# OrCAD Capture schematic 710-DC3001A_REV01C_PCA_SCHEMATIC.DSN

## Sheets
1 PAGE2: size A; company: ANALOG DEVICES; note: DEMO BOARD BILL OF MATERIALS; note: LOW QUIESCENT CURRENT IDEAL DIODE WITH SHUTDOWN MODE
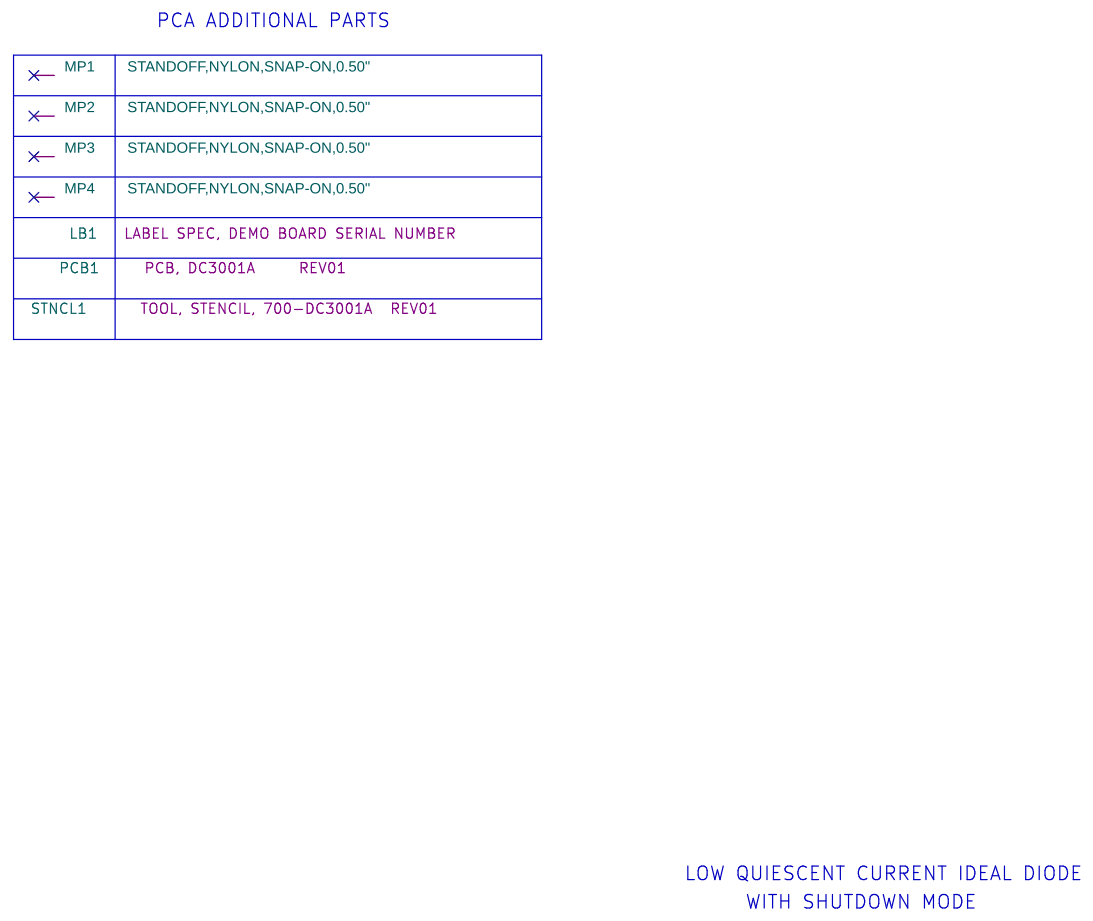
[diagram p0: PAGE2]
2 PAGE1: size Custom
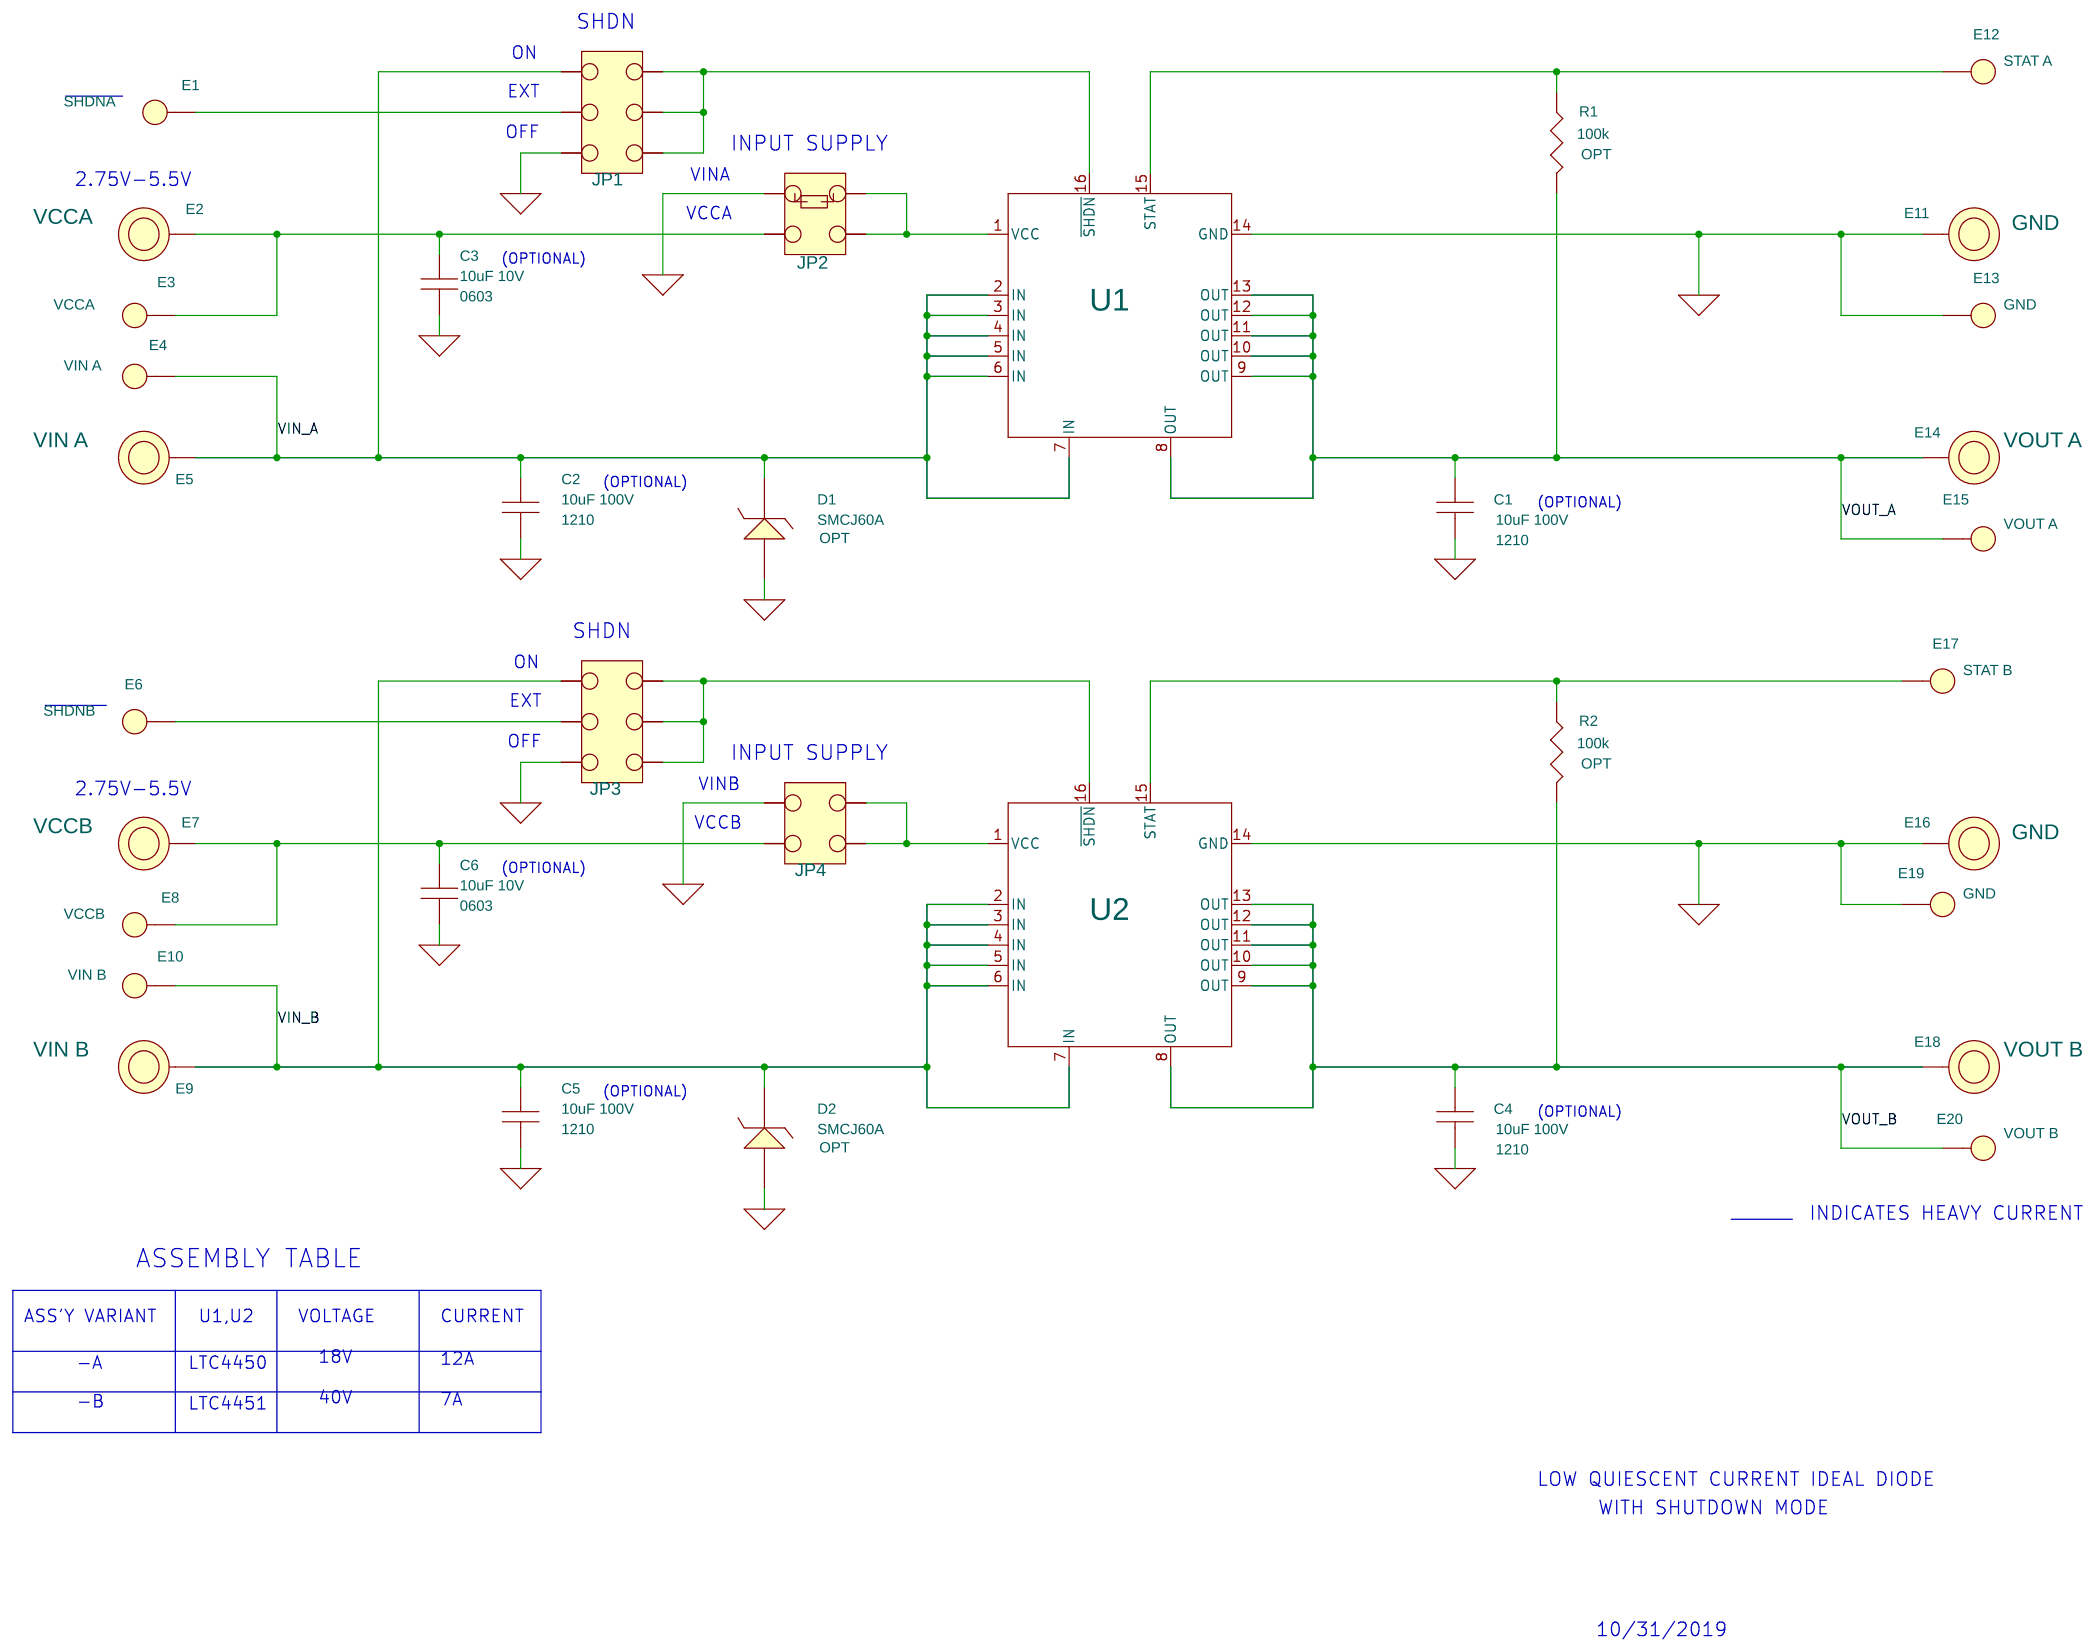
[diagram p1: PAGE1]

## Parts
sheet PAGE1
C1  OPT  [CC1210N]
C2  OPT  [CC1210N]
C3  OPT  [CC0603N]
C4  OPT  [CC1210N]
C5  OPT  [CC1210N]
C6  OPT  [CC0603N]
D1  SMCJ60A  [SMC-N]
D2  SMCJ60A  [SMC-N]
E1  TEST POINT  [MILLMAX2308-2]
E2  BANANA JACK  [KEY-575-4]
E3  TEST POINT  [MILLMAX2308-2]
E4  TEST POINT  [MILLMAX2308-2]
E5  BANANA JACK  [KEY-575-4]
E6  TEST POINT  [MILLMAX2308-2]
E7  BANANA JACK  [KEY-575-4]
E8  TEST POINT  [MILLMAX2308-2]
E9  BANANA JACK  [KEY-575-4]
E10  TEST POINT  [MILLMAX2308-2]
E11  BANANA JACK  [KEY-575-4]
E12  TEST POINT  [MILLMAX2308-2]
E13  TEST POINT  [MILLMAX2308-2]
E14  BANANA JACK  [KEY-575-4]
E15  TEST POINT  [MILLMAX2308-2]
E16  BANANA JACK  [KEY-575-4]
E17  TEST POINT  [MILLMAX2308-2]
E18  BANANA JACK  [KEY-575-4]
E19  TEST POINT  [MILLMAX2308-2]
E20  TEST POINT  [MILLMAX2308-2]
JP1  HDR.  [HD2X3-079]
JP2  HDR  [HD2X2-079]
JP3  HDR.  [HD2X3-079]
JP4  HDR  [HD2X2-079]
R1  100k  [CR0603N]
R2  100k  [CR0603N]
U1  LTC4450HUB  [LTC-LQFN-16-1683]
U2  LTC4450HUB  [LTC-LQFN-16-1683]
XJP1  SHUNT
XJP2  SHUNT
XJP3  SHUNT
XJP4  SHUNT
sheet PAGE2
LB1  LABEL  [895-0154_REV01]
MP1  STANDOFF  [KEYSTONE_8833]
MP2  STANDOFF  [KEYSTONE_8833]
MP3  STANDOFF  [KEYSTONE_8833]
MP4  STANDOFF  [KEYSTONE_8833]
PCB1  PCB, DC3001A
STNCL1  TOOL, STENCIL, DC3001A

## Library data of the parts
C1 C2 C4 C5 = CAP: CAP., OPTION, 1210; BOM Notes: 10uF 100V; CLASS: DISCRETE; FPLIST: CC1210N,CC1210L,CC1210M; PART_NUMBER: 150-3035; Package Size: 1210; Package Type: SMD
C3 C6 = CAP: CAP., OPTION, 0603; BOM Notes: 10uF 10V; CLASS: DISCRETE; FPLIST: CC0603N,CC0603L,CC0603M; PART_NUMBER: 150-3038; Package Size: 0603; Package Type: SMD
D1 D2 = DIODE_TVS_B_ALT: DIODE,TVS, UNIDIRECTIONAL,60V,1500W,7.12 X 6.23 DO-214-AB,J-LEAD; CLASS: DISCRETE; Inventory Qty: 0; Manufacturer: AVX; PART_FIELD_01: OPT; PART_NUMBER: 210-0487; Package Type: 7.12 X 6.23 DO-214-AB; Rated Voltage or Zener Voltage: 60V
E1 = TEST_POINT_.156_MILL-MAX_2308: TEST POINT,TURRET,0.064" MTG. HOLE,PCB 0.062" THK; CLASS: IO; FPLIST: MILLMAX2308,MILLMAX2308-2; Inventory Qty: 719221; Manufacturer: MILL-MAX; Manufacturer PN: 2308-2-00-80-00-00-07-0; PART_FIELD_1: SHDNA; PART_NUMBER: 260-0004
E2 = BANANA_KEYSTONE-575-4: CONN.,BANANA JACK,FEMALE,THT,NON-INSULATED,SWAGE,0.218"; CLASS: IO; Inventory Qty: 184137; Manufacturer: KEYSTONE; Manufacturer PN: 575-4; PART_FIELD_01: VCCA; PART_NUMBER: 250-0428
E3 = TEST_POINT_.156_MILL-MAX_2308: TEST POINT,TURRET,0.064" MTG. HOLE,PCB 0.062" THK; CLASS: IO; FPLIST: MILLMAX2308,MILLMAX2308-2; Inventory Qty: 719221; Manufacturer: MILL-MAX; Manufacturer PN: 2308-2-00-80-00-00-07-0; PART_FIELD_1: VCCA; PART_NUMBER: 260-0004
E4 = TEST_POINT_.156_MILL-MAX_2308: TEST POINT,TURRET,0.064" MTG. HOLE,PCB 0.062" THK; CLASS: IO; FPLIST: MILLMAX2308,MILLMAX2308-2; Inventory Qty: 719221; Manufacturer: MILL-MAX; Manufacturer PN: 2308-2-00-80-00-00-07-0; PART_FIELD_1: VIN A; PART_NUMBER: 260-0004
E5 = BANANA_KEYSTONE-575-4: CONN.,BANANA JACK,FEMALE,THT,NON-INSULATED,SWAGE,0.218"; CLASS: IO; Inventory Qty: 184137; Manufacturer: KEYSTONE; Manufacturer PN: 575-4; PART_FIELD_01: 1.9V-27.5V; PART_FIELD_02: VIN A; PART_NUMBER: 250-0428
E6 = TEST_POINT_.156_MILL-MAX_2308: TEST POINT,TURRET,0.064" MTG. HOLE,PCB 0.062" THK; CLASS: IO; FPLIST: MILLMAX2308,MILLMAX2308-2; Inventory Qty: 719221; Manufacturer: MILL-MAX; Manufacturer PN: 2308-2-00-80-00-00-07-0; PART_FIELD_1: SHDNB; PART_NUMBER: 260-0004
E7 = BANANA_KEYSTONE-575-4: CONN.,BANANA JACK,FEMALE,THT,NON-INSULATED,SWAGE,0.218"; CLASS: IO; Inventory Qty: 184137; Manufacturer: KEYSTONE; Manufacturer PN: 575-4; PART_FIELD_01: VCCB; PART_NUMBER: 250-0428
E8 = TEST_POINT_.156_MILL-MAX_2308: TEST POINT,TURRET,0.064" MTG. HOLE,PCB 0.062" THK; CLASS: IO; FPLIST: MILLMAX2308,MILLMAX2308-2; Inventory Qty: 719221; Manufacturer: MILL-MAX; Manufacturer PN: 2308-2-00-80-00-00-07-0; PART_FIELD_1: VCCB; PART_NUMBER: 260-0004
E9 = BANANA_KEYSTONE-575-4: CONN.,BANANA JACK,FEMALE,THT,NON-INSULATED,SWAGE,0.218"; CLASS: IO; Inventory Qty: 184137; Manufacturer: KEYSTONE; Manufacturer PN: 575-4; PART_FIELD_01: 1.9V-27.5V; PART_FIELD_02: VIN B; PART_NUMBER: 250-0428
E10 = TEST_POINT_.156_MILL-MAX_2308: TEST POINT,TURRET,0.064" MTG. HOLE,PCB 0.062" THK; CLASS: IO; FPLIST: MILLMAX2308,MILLMAX2308-2; Inventory Qty: 719221; Manufacturer: MILL-MAX; Manufacturer PN: 2308-2-00-80-00-00-07-0; PART_FIELD_1: VIN B; PART_NUMBER: 260-0004
E11 E16 = BANANA_KEYSTONE-575-4: CONN.,BANANA JACK,FEMALE,THT,NON-INSULATED,SWAGE,0.218"; CLASS: IO; Inventory Qty: 184137; Manufacturer: KEYSTONE; Manufacturer PN: 575-4; PART_FIELD_01: GND; PART_NUMBER: 250-0428
E12 = TEST_POINT_.156_MILL-MAX_2308: TEST POINT,TURRET,0.064" MTG. HOLE,PCB 0.062" THK; CLASS: IO; FPLIST: MILLMAX2308,MILLMAX2308-2; Inventory Qty: 719221; Manufacturer: MILL-MAX; Manufacturer PN: 2308-2-00-80-00-00-07-0; PART_FIELD_1: STAT A; PART_NUMBER: 260-0004
E13 E19 = TEST_POINT_.156_MILL-MAX_2308: TEST POINT,TURRET,0.064" MTG. HOLE,PCB 0.062" THK; CLASS: IO; FPLIST: MILLMAX2308,MILLMAX2308-2; Inventory Qty: 719221; Manufacturer: MILL-MAX; Manufacturer PN: 2308-2-00-80-00-00-07-0; PART_FIELD_1: GND; PART_NUMBER: 260-0004
E14 = BANANA_KEYSTONE-575-4: CONN.,BANANA JACK,FEMALE,THT,NON-INSULATED,SWAGE,0.218"; CLASS: IO; Inventory Qty: 184137; Manufacturer: KEYSTONE; Manufacturer PN: 575-4; PART_FIELD_01: 1.9V-27.5V; PART_FIELD_02: VOUT A; PART_NUMBER: 250-0428
E15 = TEST_POINT_.156_MILL-MAX_2308: TEST POINT,TURRET,0.064" MTG. HOLE,PCB 0.062" THK; CLASS: IO; FPLIST: MILLMAX2308,MILLMAX2308-2; Inventory Qty: 719221; Manufacturer: MILL-MAX; Manufacturer PN: 2308-2-00-80-00-00-07-0; PART_FIELD_1: VOUT A; PART_NUMBER: 260-0004
E17 = TEST_POINT_.156_MILL-MAX_2308: TEST POINT,TURRET,0.064" MTG. HOLE,PCB 0.062" THK; CLASS: IO; FPLIST: MILLMAX2308,MILLMAX2308-2; Inventory Qty: 719221; Manufacturer: MILL-MAX; Manufacturer PN: 2308-2-00-80-00-00-07-0; PART_FIELD_1: STAT B; PART_NUMBER: 260-0004
E18 = BANANA_KEYSTONE-575-4: CONN.,BANANA JACK,FEMALE,THT,NON-INSULATED,SWAGE,0.218"; CLASS: IO; Inventory Qty: 184137; Manufacturer: KEYSTONE; Manufacturer PN: 575-4; PART_FIELD_01: 1.9V-27.5V; PART_FIELD_02: VOUT B; PART_NUMBER: 250-0428
E20 = TEST_POINT_.156_MILL-MAX_2308: TEST POINT,TURRET,0.064" MTG. HOLE,PCB 0.062" THK; CLASS: IO; FPLIST: MILLMAX2308,MILLMAX2308-2; Inventory Qty: 719221; Manufacturer: MILL-MAX; Manufacturer PN: 2308-2-00-80-00-00-07-0; PART_FIELD_1: VOUT B; PART_NUMBER: 260-0004
JP1 JP3 = HEADER_2X3_.079: CONN.,HDR.,MALE,2x3,2mm,VERT,STR,THT; CLASS: IO; Inventory Qty: 25771; Manufacturer: SAMTEC; Manufacturer PN: TMM-103-02-L-D; PART_NUMBER: 250-0423
JP2 JP4 = HEADER_2X2_.079: CONN.,HDR,MALE,2x2,2mm,VERT,ST,THT,10u" Au; CLASS: IO; Inventory Qty: 21786; Manufacturer: SAMTEC; Manufacturer PN: TMM-102-02-L-D; PART_NUMBER: 250-0424
R1 R2 = RES: RES.,100k OHMS,1%,1/10W,0603; CLASS: DISCRETE; FPLIST: CR0603N,CR0603L,CR0603M; Inventory Qty: 22530; Manufacturer: YAGEO; Manufacturer PN: RC0603FR-07100KL; PART_FIELD_01: OPT; PART_NUMBER: 100-0120; Package Size: 0603; Rated Power: 1/10W; Temperature Coefficient: 100ppm/C; Tolerance: 1%
U1 U2 = LTC4450_51-LQFN: IC,IDEAL DIODE W/SHUTDOWN MODE, LQFN (PRELIMINARY PART, NOT FOR PRODUCTION); CLASS: IC; Inventory Qty: 0; Manufacturer: ANALOG DEVICES; Manufacturer PN: LTC4450HUB#PBF; PART_NUMBER: LTC4450HUB#PBF; Package Size: LQFN; Package Type: LQFN
XJP1-XJP4 = SHUNT_2MM_C: CONN.,SHUNT,FEMALE,2-POS,2mm; CLASS: IO; Inventory Qty: 87526; Manufacturer: SAMTEC; Manufacturer PN: 2SN-BK-G; PART_NUMBER: 250-0419
LB1 = BLANK_LABEL: LABEL SPEC, DEMO BOARD SERIAL NUMBER; Inventory Qty: 0; Manufacturer: BRADY; Manufacturer PN: THT-96-717-10; PART_NUMBER: 895-0154
MP1-MP4 = MP-PINNED_ALT1: STANDOFF,NYLON,SNAP-ON,0.50"; CLASS: DISCRETE; Inventory Qty: 185948; Manufacturer: KEYSTONE; Manufacturer PN: 8833; PART_NUMBER: 763-0007
PCB1 = BLANK_PCB_PART: BOM Notes: REV01; CLASS: DISCRETE; Inventory Qty: 0; Manufacturer: MAO BANG; Manufacturer PN: 600-DC3001A; PART_NUMBER: 600-DC3001A
STNCL1 = BLANK_STENCIL_PART: TOOL, STENCIL, 700-DC3001A; BOM Notes: REV01; CLASS: DISCRETE; Inventory Qty: 0; Manufacturer: ANALOG DEVICES; Manufacturer PN: 830-DC3001A; PART_NUMBER: 830-DC3001A

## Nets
GND_SIGNAL: C1.2 C2.2 C3.2 C4.2 C5.2 C6.2 D1.2(A) D2.2(A) E11.1 E13.1(A) E16.1 E19.1(A) JP1.5 JP2.1 JP3.5 JP4.1 U1.14(GND) U2.14(GND)
VIN_A: C2.1 D1.1(C) E4.1(A) E5.1 JP1.1 U1.2(IN) U1.3(IN) U1.4(IN) U1.5(IN) U1.6(IN) U1.7(IN)
VIN_B: C5.1 D2.1(C) E9.1 E10.1(A) JP3.1 U2.2(IN) U2.3(IN) U2.4(IN) U2.5(IN) U2.6(IN) U2.7(IN)
VOUT_A: C1.1 E14.1 E15.1(A) R1.2 U1.8(OUT) U1.9(OUT) U1.10(OUT) U1.11(OUT) U1.12(OUT) U1.13(OUT)
VOUT_B: C4.1 E18.1 E20.1(A) R2.2 U2.8(OUT) U2.9(OUT) U2.10(OUT) U2.11(OUT) U2.12(OUT) U2.13(OUT)
N04054: C3.1 E2.1 E3.1(A) JP2.3
N16606798: E12.1(A) R1.1 U1.15(STAT)
N16608025: JP1.2 JP1.4 JP1.6 U1.16(~{SHDN})
N16614720: E1.1(A) JP1.3
N16616083: JP2.2 JP2.4 U1.1(VCC)
N16619238: JP3.2 JP3.4 JP3.6 U2.16(~{SHDN})
N16619254: E17.1(A) R2.1 U2.15(STAT)
N16619282: E6.1(A) JP3.3
N16619358: JP4.2 JP4.4 U2.1(VCC)
N16619432: C6.1 E7.1 E8.1(A) JP4.3

Not connected (* = marked no-connect by the designer): MP1 1*; MP2 1*; MP3 1*; MP4 1*

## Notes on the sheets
sheet 1
- PCA ADDITIONAL PARTS
- LOW QUIESCENT CURRENT IDEAL DIODE
- WITH SHUTDOWN MODE
sheet 2
- SHDN
- ON
- EXT
- OFF
- INPUT SUPPLY
- 2.75V-5.5V
- VINA
- VCCA
- (OPTIONAL)
- (OPTIONAL)
- (OPTIONAL)
- SHDN
- ON
- EXT
- OFF
- INPUT SUPPLY
- 2.75V-5.5V
- VINB
- VCCB
- (OPTIONAL)
- (OPTIONAL)
- (OPTIONAL)
- INDICATES HEAVY CURRENT
- ASSEMBLY TABLE
- ASS'Y VARIANT
- U1,U2
- VOLTAGE
- CURRENT
- -A
- LTC4450
- 18V
- 12A
- -B
- LTC4451
- 40V
- 7A
- LOW QUIESCENT CURRENT IDEAL DIODE
- WITH SHUTDOWN MODE
- 10/31/2019
